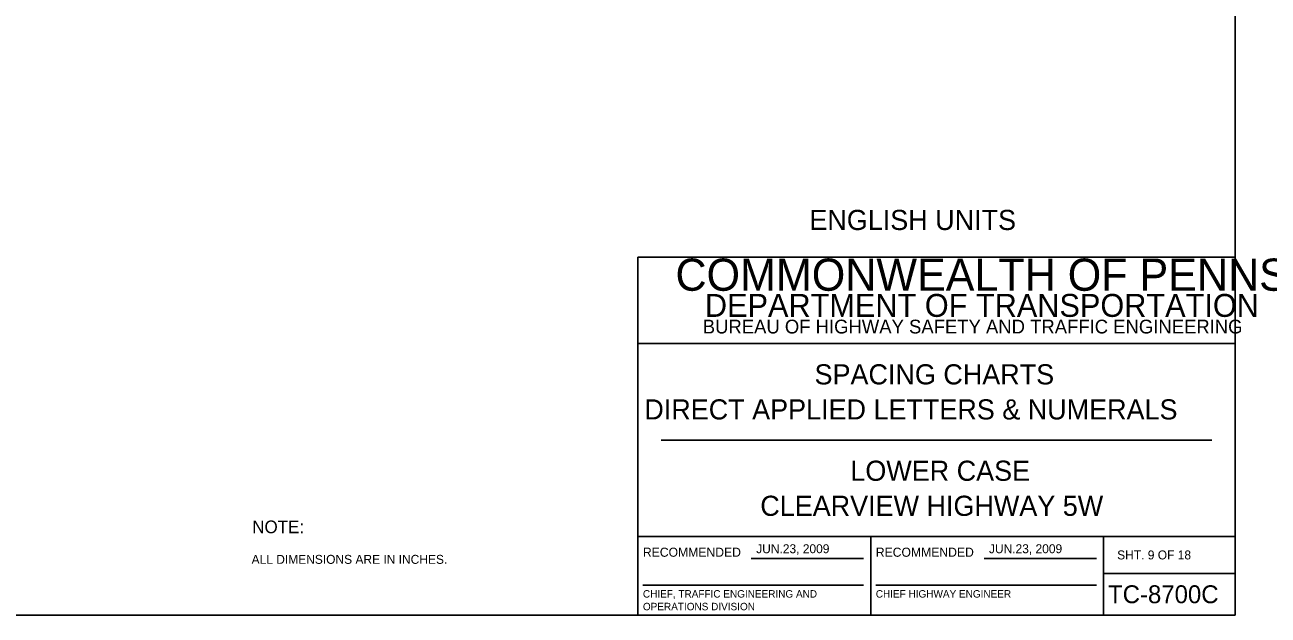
# Model space of a CAD drawing. Extents: x 637580 to 641849, y 297270 to 299646.
# Drawn here: x 639683 to 640099.4, y 299066.6 to 299264.5 of the extents above; entities that cross this region are included whole.
import ezdxf

# ---------------------------------------------------------------- set-up
doc = ezdxf.new("R2010")
doc.units = 0
doc.layers.add('1', color=7, linetype='Continuous')
doc.layers.add('2', color=7, linetype='Continuous')

msp = doc.modelspace()

# ---------------------------------------------------------------- linework, layer by layer
at = {"layer": '1'}
for p, q in [((640088.31, 299066.63), (640088.31, 299630.63)), ((639888.31, 299066.63), (639888.31, 299186.63)), ((639888.31, 299186.63), (640088.31, 299186.63)), ((640088.31, 299157.63), (639888.31, 299157.63)), ((639896.06, 299125.31), (640080.56, 299125.31)), ((639888.31, 299093), (640088.31, 299093)), ((639966.31, 299093), (639966.31, 299066.63)), ((640044.19, 299066.63), (640044.19, 299093)), ((639926.24, 299085.57), (639963.87, 299085.57)), ((640004.24, 299085.57), (640041.87, 299085.57)), ((640044.19, 299080.63), (640088.31, 299080.63)), ((639889.99, 299076.68), (639963.87, 299076.68)), ((639967.99, 299076.68), (640041.87, 299076.68)), ((640088.31, 299066.63), (639302.31, 299066.63)), ((639302.31, 299066.63), (639888.31, 299066.63))]:
    msp.add_line(p, q, dxfattribs=at)

# ---------------------------------------------------------------- texts
for s, height, p in [('COMMONWEALTH OF PENNSYLVANIA', 10.7828, (639900.9, 299175.36)), ('DEPARTMENT OF TRANSPORTATION', 7.6837, (639910.76, 299166.61)), ('BUREAU OF HIGHWAY SAFETY AND TRAFFIC ENGINEERING', 4.6253, (639910.04, 299161.04)), ('SPACING CHARTS', 6.75, (639947.47, 299143.97)), ('DIRECT APPLIED LETTERS & NUMERALS', 6.75, (639890.47, 299132.22)), ('LOWER CASE', 6.75, (639959.47, 299111.66)), ('CLEARVIEW HIGHWAY 5W', 6.75, (639929.3, 299099.91)), ('RECOMMENDED', 3.048, (639889.99, 299086.2)), ('RECOMMENDED', 3.048, (639967.99, 299086.2)), ('SHT. 9 OF 18', 3, (640048.82, 299085.31)), ('TC-8700C', 6, (640045.77, 299070.63)), ('CHIEF, TRAFFIC ENGINEERING AND', 2.5, (639889.99, 299072.51)), ('CHIEF HIGHWAY ENGINEER', 2.5, (639967.99, 299072.51)), ('OPERATIONS DIVISION', 2.5, (639889.99, 299068.26))]:
    msp.add_text(s, height=height, dxfattribs=at).set_placement(p)
at = {"layer": '2'}
for s, height, p in [('ENGLISH UNITS', 6.75, (639945.74, 299195.72)), ('NOTE:', 4.25, (639759.16, 299094.1)), ('JUN.23, 2009', 3, (639927.93, 299087.39)), ('ALL DIMENSIONS ARE IN INCHES.', 3, (639758.94, 299083.83))]:
    msp.add_text(s, height=height, dxfattribs=at).set_placement(p)
msp.add_text('JUN.23, 2009', height=3, rotation=360, dxfattribs=at).set_placement((640005.88, 299087.39))

doc.saveas('drawing.dxf')
